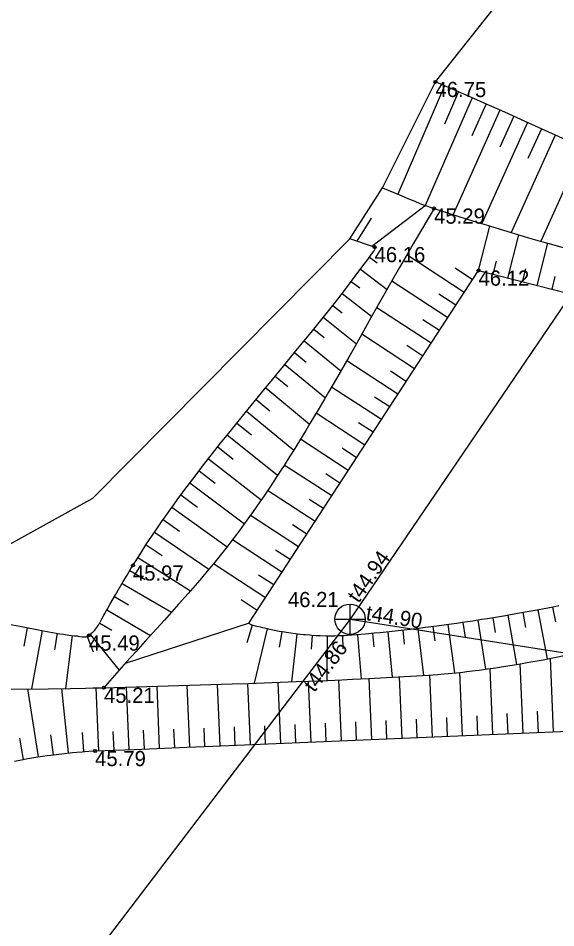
# Model space of a CAD drawing. Extents: x 561134 to 561329, y 413819 to 414116.
# Drawn here: x 561204.52 to 561222.24, y 413922.54 to 413952.49 of the extents above; entities that cross this region are included whole.
import ezdxf

# ---------------------------------------------------------------- set-up
doc = ezdxf.new("R2010")
doc.units = 0
for name, color, linetype in [('RAMI_UZMR_####_####_#', 7, 'Continuous'), ('RELJ_AATZ_####_TKST_#', 7, 'Continuous'), ('RELJ_ELEM_####_####_#', 7, 'Continuous'), ('RELJ_NOGA_####_####_#', 7, 'Continuous'), ('RELJ_NOGL_####_####_#', 7, 'Continuous'), ('SKAN_ELEM_####_####_#', 7, 'Continuous'), ('SKAN_ELEM_PAST_TKST_#', 7, 'Continuous'), ('SKAN_VADP_PAST_####_#', 7, 'Continuous'), ('SKAN_VADP_PAST_TKST_#', 7, 'Continuous')]:
    doc.layers.add(name, color=color, linetype=linetype)

msp = doc.modelspace()

# ---------------------------------------------------------------- linework, layer by layer
at = {"layer": 'RAMI_UZMR_####_####_#'}
msp.add_lwpolyline([(561188.512, 413892.082), (561185.041, 413910.753), (561191.104, 413917.736), (561189.205, 413920.568), (561187.984, 413924.22), (561187.954, 413928.121), (561192.417, 413932.029), (561202.582, 413934.262), (561206.983, 413936.681), (561215.453, 413945.229), (561216.519, 413946.905), (561218.27, 413950.393), (561229.69, 413964.77), (561237.253, 413982.653), (561235.655, 414013.737)], dxfattribs=at)
at = {"layer": 'RELJ_ELEM_####_####_#'}
for centre in [(561218.27, 413950.393), (561218.224, 413946.224), (561216.262, 413944.956), (561219.689, 413944.182), (561208.299, 413934.471), (561206.85, 413932.165), (561207.345, 413930.446), (561207.052, 413928.362)]:
    msp.add_circle(centre, 0.05, dxfattribs=at)
at = {"layer": 'RELJ_NOGA_####_####_#'}
for p, q in [((561218.565, 413950.268), (561217.029, 413946.693)), ((561219.024, 413950.071), (561218.564, 413948.999)), ((561219.482, 413949.871), (561217.933, 413946.326)), ((561219.939, 413949.668), (561219.471, 413948.62)), ((561220.396, 413949.464), (561218.855, 413946.021)), ((561221.307, 413949.053), (561219.799, 413945.725)), ((561220.852, 413949.259), (561220.393, 413948.243)), ((561221.763, 413948.846), (561221.318, 413947.866)), ((561222.218, 413948.64), (561220.765, 413945.432)), ((561223.13, 413948.229), (561221.744, 413945.145)), ((561216.168, 413944.988), (561217.933, 413946.326)), ((561215.694, 413945.148), (561216.161, 413945.904)), ((561219.689, 413944.182), (561220.062, 413945.644)), ((561220.658, 413943.935), (561221.02, 413945.357)), ((561221.627, 413943.689), (561221.978, 413945.078)), ((561216.096, 413944.623), (561216.347, 413944.439)), ((561219.219, 413943.461), (561217.325, 413944.696)), ((561219.492, 413943.88), (561218.917, 413944.255)), ((561220.174, 413944.058), (561220.284, 413944.491)), ((561215.798, 413944.221), (561216.677, 413943.561)), ((561221.143, 413943.812), (561221.249, 413944.233)), ((561222.112, 413943.568), (561222.216, 413943.98)), ((561215.497, 413943.822), (561215.775, 413943.61)), ((561218.673, 413942.623), (561216.828, 413943.826)), ((561215.191, 413943.427), (561216.169, 413942.663)), ((561218.946, 413943.042), (561218.385, 413943.408)), ((561214.883, 413943.033), (561215.193, 413942.788)), ((561218.127, 413941.786), (561216.334, 413942.954)), ((561214.572, 413942.642), (561215.664, 413941.77)), ((561218.4, 413942.205), (561217.854, 413942.56)), ((561214.258, 413942.252), (561214.604, 413941.973)), ((561213.943, 413941.864), (561215.153, 413940.876)), ((561217.581, 413940.948), (561215.841, 413942.082)), ((561217.854, 413941.367), (561217.324, 413941.712)), ((561213.627, 413941.477), (561214.008, 413941.164)), ((561213.309, 413941.091), (561214.642, 413939.995)), ((561217.034, 413940.11), (561215.345, 413941.212)), ((561212.992, 413940.705), (561213.409, 413940.361)), ((561217.307, 413940.529), (561216.793, 413940.864)), ((561212.674, 413940.319), (561214.123, 413939.124)), ((561216.488, 413939.273), (561214.845, 413940.344)), ((561212.356, 413939.932), (561212.808, 413939.562)), ((561216.761, 413939.692), (561216.262, 413940.017)), ((561212.039, 413939.546), (561213.597, 413938.268)), ((561215.942, 413938.435), (561214.337, 413939.481)), ((561211.724, 413939.158), (561212.206, 413938.766)), ((561216.215, 413938.854), (561215.728, 413939.171)), ((561211.409, 413938.769), (561213.069, 413937.441)), ((561215.396, 413937.597), (561213.819, 413938.625)), ((561211.098, 413938.378), (561211.608, 413937.974)), ((561215.669, 413938.016), (561215.192, 413938.327)), ((561210.788, 413937.985), (561212.529, 413936.633)), ((561214.85, 413936.76), (561213.287, 413937.778)), ((561210.482, 413937.59), (561211.012, 413937.182)), ((561215.123, 413937.178), (561214.653, 413937.485)), ((561210.179, 413937.192), (561211.974, 413935.843)), ((561209.881, 413936.791), (561210.423, 413936.391)), ((561214.304, 413935.922), (561212.739, 413936.942)), ((561214.577, 413936.341), (561214.108, 413936.646)), ((561209.586, 413936.387), (561211.402, 413935.084)), ((561209.296, 413935.979), (561209.838, 413935.599)), ((561213.758, 413935.084), (561212.171, 413936.118)), ((561209.013, 413935.568), (561210.806, 413934.35)), ((561214.031, 413935.503), (561213.559, 413935.811)), ((561213.211, 413934.247), (561211.578, 413935.311)), ((561208.734, 413935.152), (561209.263, 413934.802)), ((561213.484, 413934.665), (561213.003, 413934.979)), ((561208.463, 413934.732), (561210.192, 413933.634)), ((561212.665, 413933.409), (561210.952, 413934.526)), ((561208.199, 413934.308), (561208.707, 413934.003)), ((561212.938, 413933.828), (561212.437, 413934.154)), ((561207.945, 413933.877), (561209.572, 413932.936)), ((561207.695, 413933.444), (561208.153, 413933.176)), ((561212.392, 413932.99), (561211.863, 413933.335)), ((561207.44, 413933.014), (561208.877, 413932.167)), ((561221.149, 413932.916), (561221.236, 413932.431)), ((561221.641, 413933.005), (561221.948, 413931.393)), ((561222.132, 413933.099), (561222.224, 413932.616)), ((561207.203, 413932.574), (561207.607, 413932.344)), ((561212.133, 413932.567), (561208.04, 413931.239)), ((561219.175, 413932.592), (561219.247, 413932.112)), ((561219.67, 413932.667), (561219.92, 413931.055)), ((561220.163, 413932.746), (561220.243, 413932.261)), ((561220.657, 413932.829), (561220.937, 413931.212)), ((561204.818, 413932.42), (561204.701, 413931.814)), ((561205.309, 413932.325), (561204.956, 413930.406)), ((561212.234, 413932.504), (561212.058, 413931.924)), ((561212.719, 413932.382), (561212.298, 413930.593)), ((561213.209, 413932.284), (561213.119, 413931.783)), ((561216.695, 413932.282), (561216.847, 413930.791)), ((561217.192, 413932.335), (561217.243, 413931.881)), ((561217.689, 413932.393), (561217.871, 413930.852)), ((561218.185, 413932.455), (561218.245, 413931.985)), ((561218.68, 413932.522), (561218.896, 413930.933)), ((561205.801, 413932.238), (561205.711, 413931.69)), ((561206.296, 413932.167), (561206.079, 413930.42)), ((561206.791, 413932.133), (561206.99, 413931.628)), ((561206.885, 413932.192), (561207.843, 413931.017)), ((561213.703, 413932.211), (561213.521, 413930.638)), ((561214.201, 413932.165), (561214.175, 413931.714)), ((561214.701, 413932.146), (561214.685, 413930.686)), ((561215.201, 413932.154), (561215.221, 413931.721)), ((561215.699, 413932.189), (561215.822, 413930.738)), ((561216.197, 413932.233), (561216.238, 413931.792)), ((561222.164, 413928.994), (561222.057, 413931.414)), ((561220.165, 413928.907), (561220.072, 413931.077)), ((561221.165, 413928.951), (561221.064, 413931.233)), ((561217.168, 413928.778), (561217.083, 413930.805)), ((561218.167, 413928.821), (561218.08, 413930.865)), ((561219.166, 413928.864), (561219.077, 413930.951)), ((561209.175, 413928.448), (561209.094, 413930.495)), ((561210.174, 413928.488), (561210.092, 413930.524)), ((561211.173, 413928.529), (561211.09, 413930.554)), ((561212.173, 413928.57), (561212.089, 413930.586)), ((561213.172, 413928.611), (561213.089, 413930.621)), ((561214.171, 413928.653), (561214.088, 413930.66)), ((561215.17, 413928.694), (561215.085, 413930.703)), ((561216.169, 413928.736), (561216.084, 413930.751)), ((561205.188, 413928.167), (561204.833, 413930.405)), ((561206.179, 413928.298), (561205.954, 413930.418)), ((561207.177, 413928.367), (561207.091, 413930.44)), ((561208.176, 413928.408), (561208.091, 413930.467)), ((561220.665, 413928.929), (561220.636, 413929.596)), ((561221.664, 413928.972), (561221.633, 413929.677)), ((561214.67, 413928.673), (561214.646, 413929.276)), ((561215.67, 413928.715), (561215.644, 413929.319)), ((561216.669, 413928.757), (561216.643, 413929.363)), ((561217.668, 413928.8), (561217.642, 413929.41)), ((561218.667, 413928.843), (561218.64, 413929.461)), ((561219.666, 413928.885), (561219.639, 413929.523)), ((561207.676, 413928.388), (561207.651, 413929.007)), ((561208.675, 413928.428), (561208.651, 413929.044)), ((561209.675, 413928.468), (561209.65, 413929.08)), ((561210.674, 413928.508), (561210.649, 413929.117)), ((561211.673, 413928.549), (561211.648, 413929.155)), ((561212.672, 413928.591), (561212.647, 413929.195)), ((561213.671, 413928.632), (561213.646, 413929.234)), ((561204.695, 413928.084), (561204.571, 413928.778)), ((561205.683, 413928.239), (561205.597, 413928.89)), ((561206.677, 413928.341), (561206.633, 413928.967))]:
    msp.add_line(p, q, dxfattribs=at)
for points in [[(561222.57, 413948.481), (561221.224, 413949.091), (561220.551, 413949.395), (561219.877, 413949.696), (561219.539, 413949.846), (561219.033, 413950.067), (561218.524, 413950.285), (561218.27, 413950.393)], [(561206.885, 413932.192), (561206.908, 413932.21), (561206.95, 413932.248), (561206.97, 413932.267), (561207.009, 413932.306), (561207.044, 413932.345), (561207.067, 413932.372), (561207.109, 413932.427), (561207.152, 413932.49), (561207.179, 413932.533), (561207.196, 413932.562), (561207.23, 413932.62), (561207.277, 413932.709), (561207.338, 413932.828), (561207.369, 413932.888), (561207.419, 413932.977), (561207.445, 413933.021), (561207.541, 413933.182), (561207.73, 413933.505), (561207.98, 413933.937), (561208.106, 413934.152), (561208.234, 413934.365), (561208.299, 413934.471), (561208.384, 413934.606), (561208.555, 413934.876), (561208.729, 413935.144), (561208.846, 413935.321), (561208.925, 413935.439), (561209.085, 413935.674), (561209.266, 413935.937), (561209.389, 413936.111), (561209.471, 413936.227), (561209.637, 413936.458), (561209.762, 413936.63), (561210.015, 413936.973), (561210.271, 413937.314), (561210.444, 413937.541), (561210.56, 413937.691), (561210.793, 413937.991), (561210.924, 413938.159), (561211.19, 413938.494), (561211.457, 413938.828), (561211.636, 413939.05), (561211.996, 413939.493), (561212.539, 413940.156), (561213.266, 413941.037), (561213.628, 413941.479), (561213.99, 413941.921), (561214.17, 413942.142), (561214.439, 413942.475), (561214.795, 413942.921), (561214.972, 413943.145), (561215.235, 413943.482), (561215.496, 413943.821), (561215.625, 413943.991), (561215.881, 413944.332), (561216.009, 413944.504), (561216.198, 413944.762), (561216.241, 413944.823), (561216.262, 413944.858), (561216.274, 413944.881), (561216.278, 413944.892), (561216.283, 413944.908), (561216.285, 413944.921), (561216.285, 413944.927), (561216.283, 413944.935), (561216.28, 413944.942), (561216.278, 413944.945), (561216.272, 413944.951), (561216.269, 413944.953), (561216.262, 413944.956), (561215.453, 413945.229)], [(561212.133, 413932.567), (561212.131, 413932.572), (561212.131, 413932.577), (561212.132, 413932.588), (561212.134, 413932.593), (561212.139, 413932.602), (561219.689, 413944.182)], [(561219.689, 413944.182), (561220.854, 413943.885), (561221.632, 413943.688), (561223.187, 413943.297), (561225.26, 413942.776), (561226.296, 413942.512), (561227.331, 413942.246), (561227.848, 413942.112), (561228.538, 413941.931), (561228.882, 413941.84), (561229.398, 413941.702), (561230.172, 413941.492), (561230.562, 413941.385), (561231.34, 413941.169), (561232.117, 413940.949), (561232.635, 413940.802), (561233.67, 413940.503), (561234.188, 413940.353), (561235.221, 413940.05), (561236.255, 413939.745), (561237.632, 413939.337), (561238.321, 413939.134), (561239.871, 413938.678), (561240.647, 413938.452)], [(561222.341, 413933.14), (561222.145, 413933.102), (561221.622, 413933.002), (561221.361, 413932.954), (561220.969, 413932.883), (561220.577, 413932.815), (561220.38, 413932.782), (561219.988, 413932.717), (561219.792, 413932.686), (561219.497, 413932.641), (561219.148, 413932.588), (561218.974, 413932.563), (561218.712, 413932.526), (561218.319, 413932.473), (561217.926, 413932.422), (561217.729, 413932.398), (561217.336, 413932.351), (561217.139, 413932.329), (561216.844, 413932.297), (561216.451, 413932.257), (561216.254, 413932.238), (561215.959, 413932.211), (561215.515, 413932.174), (561215.362, 413932.163), (561215.259, 413932.157), (561215.191, 413932.154), (561215.054, 413932.149), (561214.951, 413932.146), (561214.883, 413932.146), (561214.745, 413932.145), (561214.654, 413932.146), (561214.471, 413932.151), (561214.333, 413932.157), (561214.196, 413932.165), (561214.127, 413932.17), (561213.989, 413932.181), (561213.92, 413932.187), (561213.817, 413932.198), (561213.662, 413932.216), (561213.507, 413932.237), (561213.429, 413932.248), (561213.292, 413932.27), (561213.223, 413932.281), (561213.12, 413932.3), (561212.965, 413932.33), (561212.81, 413932.362), (561212.732, 413932.379), (561212.578, 413932.416), (561212.5, 413932.435), (561212.385, 413932.465), (561212.337, 413932.476), (561212.263, 413932.495), (561212.227, 413932.506), (561212.227, 413932.506), (561212.193, 413932.519), (561212.179, 413932.526), (561212.159, 413932.537), (561212.146, 413932.548), (561212.14, 413932.553), (561212.134, 413932.562), (561212.133, 413932.567)], [(561204.213, 413932.534), (561204.573, 413932.467), (561205.292, 413932.328), (561205.532, 413932.284), (561205.652, 413932.263), (561205.891, 413932.224), (561206.011, 413932.205), (561206.191, 413932.18), (561206.371, 413932.158), (561206.461, 413932.148), (561206.49, 413932.144), (561206.548, 413932.134), (561206.626, 413932.121), (561206.665, 413932.117), (561206.704, 413932.117), (561206.724, 413932.118), (561206.749, 413932.121), (561206.762, 413932.124), (561206.781, 413932.129), (561206.809, 413932.14), (561206.836, 413932.156), (561206.85, 413932.165), (561206.885, 413932.192)], [(561204.393, 413928.028), (561204.571, 413928.061), (561204.838, 413928.109), (561205.104, 413928.154), (561205.238, 413928.175), (561205.476, 413928.211), (561205.595, 413928.227), (561205.773, 413928.251), (561206.041, 413928.283), (561206.221, 413928.302), (561206.31, 413928.311), (561206.445, 413928.323), (561206.624, 413928.337), (561206.714, 413928.343), (561206.849, 413928.352), (561207.052, 413928.362), (561208.346, 413928.415), (561210.073, 413928.484), (561210.936, 413928.519), (561215.102, 413928.691), (561217.186, 413928.779), (561220.311, 413928.913), (561223.436, 413929.05)]]:
    msp.add_lwpolyline(points, dxfattribs=at)
at = {"layer": 'RELJ_NOGL_####_####_#'}
for points in [[(561216.519, 413946.905), (561216.708, 413946.828), (561217.084, 413946.669), (561217.419, 413946.529), (561217.587, 413946.46), (561217.756, 413946.393), (561217.84, 413946.36), (561218.01, 413946.297), (561218.095, 413946.267), (561218.224, 413946.224), (561218.506, 413946.133), (561219.07, 413945.952), (561219.635, 413945.775), (561220.013, 413945.659), (561220.265, 413945.582), (561220.769, 413945.431), (561221.338, 413945.263), (561221.717, 413945.153), (561221.97, 413945.08), (561222.477, 413944.936)], [(561218.224, 413946.224), (561217.993, 413945.839), (561217.841, 413945.581), (561217.538, 413945.063), (561217.388, 413944.804), (561217.089, 413944.284), (561216.792, 413943.763), (561216.2, 413942.718), (561215.674, 413941.789), (561215.411, 413941.325), (561215.012, 413940.631), (561214.745, 413940.171), (561214.61, 413939.941), (561214.407, 413939.597), (561214.133, 413939.14), (561213.995, 413938.913), (561213.787, 413938.573), (561213.576, 413938.234), (561213.47, 413938.065), (561213.28, 413937.767), (561213.184, 413937.618), (561213.039, 413937.395), (561212.82, 413937.063), (561212.598, 413936.733), (561212.485, 413936.568), (561212.258, 413936.242), (561212.144, 413936.079), (561211.97, 413935.837), (561211.815, 413935.625), (561211.711, 413935.485), (561211.64, 413935.392), (561211.498, 413935.207), (561211.391, 413935.069), (561211.173, 413934.796), (561210.951, 413934.524), (561210.802, 413934.345), (561210.702, 413934.226), (561210.499, 413933.988), (561210.27, 413933.723), (561210.116, 413933.547), (561209.805, 413933.196), (561209.649, 413933.022), (561209.335, 413932.673), (561208.706, 413931.978), (561208.391, 413931.631), (561208.078, 413931.282), (561207.922, 413931.107), (561207.69, 413930.844), (561207.459, 413930.579), (561207.345, 413930.446)], [(561204.038, 413930.396), (561205.508, 413930.412), (561206.243, 413930.422), (561206.733, 413930.431), (561206.978, 413930.437), (561207.345, 413930.446), (561209.458, 413930.505), (561210.515, 413930.536), (561211.571, 413930.569), (561212.099, 413930.586), (561213.155, 413930.624), (561213.683, 413930.644), (561214.476, 413930.676), (561215.18, 413930.707), (561215.532, 413930.724), (561216.06, 413930.75), (561216.852, 413930.792), (561217.644, 413930.837), (561218.04, 413930.862), (561218.348, 413930.884), (561218.554, 413930.9), (561218.691, 413930.913), (561218.964, 413930.939), (561219.169, 413930.961), (561219.305, 413930.977), (561219.578, 413931.01), (561219.714, 413931.027), (561219.986, 413931.064), (561220.257, 413931.104), (561220.438, 413931.131), (561220.8, 413931.189), (561221.003, 413931.223), (561221.409, 413931.294), (561221.815, 413931.368), (561222.085, 413931.419), (561222.625, 413931.525)]]:
    msp.add_lwpolyline(points, dxfattribs=at)
at = {"layer": 'SKAN_ELEM_####_####_#'}
for p, q in [((561215.454, 413932.2), (561215.454, 413933.2)), ((561214.954, 413932.7), (561215.954, 413932.7))]:
    msp.add_line(p, q, dxfattribs=at)
msp.add_circle((561215.454, 413932.7), 0.5, dxfattribs=at)
at = {"layer": 'SKAN_VADP_PAST_####_#'}
msp.add_line((561234.729, 413961.018), (561215.454, 413932.7), dxfattribs=at)
for points in [[(561215.454, 413932.7), (561193.267, 413903.604)], [(561215.454, 413932.7), (561234.374, 413929.736)]]:
    msp.add_lwpolyline(points, dxfattribs=at)

# ---------------------------------------------------------------- texts
at = {"layer": 'RELJ_AATZ_####_TKST_#'}
for s, p in [('46.75', (561218.27, 413949.893)), ('45.29', (561218.224, 413945.724)), ('46.16', (561216.262, 413944.456)), ('46.12', (561219.689, 413943.682)), ('45.97', (561208.299, 413933.971)), ('45.49', (561206.85, 413931.665)), ('45.21', (561207.345, 413929.946)), ('45.79', (561207.052, 413927.862))]:
    msp.add_text(s, height=0.5, dxfattribs=at).set_placement(p)
at = {"layer": 'SKAN_ELEM_PAST_TKST_#'}
msp.add_text('46.21', height=0.5, dxfattribs=at).set_placement((561213.407, 413933.098))
at = {"layer": 'SKAN_VADP_PAST_TKST_#'}
for s, rotation, p in [('t44.94', 54.8421, (561215.734, 413933.206)), ('t44.90', 351.0971, (561215.957, 413932.676)), ('t44.86', 52.6729, (561214.276, 413930.266))]:
    msp.add_text(s, height=0.5, rotation=rotation, dxfattribs=at).set_placement(p)

doc.saveas('drawing.dxf')
